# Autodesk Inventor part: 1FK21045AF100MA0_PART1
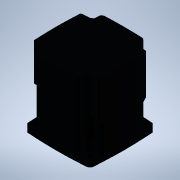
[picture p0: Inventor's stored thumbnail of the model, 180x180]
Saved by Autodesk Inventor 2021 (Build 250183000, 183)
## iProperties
Created: 2025-04
Part Number: 1FK21045AF100MA0_PART1
Material: Generic
Catalog Web Link: www.3dfindit.com
Description: -Servo synchronous motor
Document SubType Name: Modeling
Designer: psAdmin
Mass: 473.602 g
Surface Area: 436.509 cm^2
Volume: 473.602 cm^3
Density: 1 g/cm^3
Appearance: PSOLRGB-176-176-176
Category: PARTsolutions
Title: 1FK21045AF100MA0_PART1
Author: Cadenas PARTsolutions
Comments: Servo synchronous motor
Sending System: PARTsolutions
Preprocessor: ST-DEVELOPER v19.3
PSOL_IDENT_0: {$CADENAS_DATA/23d-libs/siemens_ag/_cat_/52/6b/1fk21045af100ma0.prj},213 {VTYP=3D},{NB=1FK21045AF100
PSOL_IDENT_1: MA0_PART1},{LINA=1FK21045AF100MA0_PART1},{NN=1FK21045AF100MA0_PART1},{NOPRJ=TRUE},{DATE=19.08.2025 1
PSOL_IDENT_2: 4:00:38},{GEOMDATE=30.07.2025 02:01:45},{VERSION=},{LINEID=10},{WBVAR=},{WBNUMERIC=}  {NB=1FK21045AF
PSOL_IDENT_3: 100MA0_PART1},{LINA=1FK21045AF100MA0_PART1},{KT=DUMMY},{PREVIEW=../../../_pool_/cb/72/p_d211_xx_0043
PSOL_IDENT_4: 4j.png},{DESCSHORT=SIMOTICS S-1FK2 HD, SINAMICS S210 3AC 400V-480V, 2.4 Nm, 3000 rpm},{DESCLONG=SIMO
PSOL_IDENT_5: TICS S-1FK2 HD servo motor M0=2.4 Nm; PN = 0.75 kW at nN=3000 rpm (380-480 V); PN = 0.375 kW at nN=1
PSOL_IDENT_6: 500 rpm (200-240 V); with holding brake; degree of protection IP64; cylindrical shaft D19x40mm; abso
PSOL_IDENT_7: lute encoder 22-bit + 12-bit multiturn (encoder AM22DQC); with OCC interface; plug size M17, rotatab
PSOL_IDENT_8: le; SIMOTICS S-1FK2 servomotorfor a wide range of uses in industrial environments. SIMOTICS S‑1FK2 s
PSOL_IDENT_9: ervomotors are compact synchronous motors with a high dynamic performance that set themselves apart
PSOL_IDENT_10: as a result of their high power density, degree of protection and overload capability. The motors ar
PSOL_IDENT_11: e available in two variants: as High Dynamic variant (highest dynamic performance as a result of the
PSOL_IDENT_12: low intrinsic moment of inertia for applications demanding a high dynamic performance with low move
PSOL_IDENT_13: d masses) - and as Compact variant (precise and stable closed-loop control for medium up to large mo
PSOL_IDENT_14: ved masses as a result of a medium intrinsic moment of inertia). SIMOTICSS‑1FK2 servomotors fully ex
PSOL_IDENT_15: ploit their strengths in a system with the SINAMICSS210 frequency converter and simple connection us
PSOL_IDENT_16: ing the one cable connection (OCC). Advantages include the short control and positioning times, fast
PSOL_IDENT_17: and precise correction of disturbing quantities as well as stable control with a high dynamic perfo
PSOL_IDENT_18: rmance. The servo motors can be configured to address a wide range of requirements. For example with
PSOL_IDENT_19: and without holding brake, IP64 or IP65 degree of protection, singleturn or multiturn absolute enco
PSOL_IDENT_20: ders - to name just a few. Further, the servomotors are available in different shaft heights extendi
PSOL_IDENT_21: ng from 20 to 100. A shaft sealing ring is available to achieve an IP65 degree of protection and for
PSOL_IDENT_22: subsequent mounting at the motor or as spare part. SIMOTICS - the optimum motor for each and every
PSOL_IDENT_23: motion control application.},{INTNO=804766906411},{SUPPLIERALTNO=1FK2104-5AF10-0MA0},{MANUID=1FK2104
PSOL_IDENT_24: 5AF100MA0},{MANUNAME=Siemens},{MANUTYPEDESC=Synchronous motor 1FK2-HD 2.4 NM},{AAU732=SIMOTICS},{AAO
PSOL_IDENT_25: 057=S-1FK2},{AAU734=SIMOTICS S-1FK2 HD servo motor M0=2.4 Nm; PN = 0.75 kW at nN=3000 rpm (380-480 V
PSOL_IDENT_26: ); PN = 0.375 kW at nN=1500 rpm (200-240 V); with holding brake; degree of protection IP64; cylindri
PSOL_IDENT_27: cal shaft D19x40mm; absolute encoder 22-bit + 12-bit multiturn (encoder AM22DQC); with OCC interface
PSOL_IDENT_28: ; plug size M17, rotatable;},{AAW338=Synchronous motor 1FK2-HD 2.4 NM},{AAO742=SIMOTICS},{AAO663=404
PSOL_IDENT_29: 2948693070},{NOCUPEROU=1},{PRICEQUANTITY=1},{QUANTITYMIN=1},{QUANTITYINT=1},{CTN=85015100},{COO=DE},
PSOL_IDENT_30: {AAO676=1FK2104-5AF10-0MA0},{AAO677=Siemens AG},{ORDERUNIT=C62},{CONTENTUNIT=C62}
NB: 1FK21045AF100MA0_PART1
NT: Servo synchronous motor
NBSYN: $MANUID._PART1
LINA: 1FK21045AF100MA0_PART1
CATALOG: SIEMENS
PREVIEW: ../../../_pool_/cb/72/p_d211_xx_00434j.png
DESCSHORT: SIMOTICS S-1FK2 HD, SINAMICS S210 3AC 400V-480V, 2.4 Nm, 3000 rpm
DESCLONG: SIMOTICS S-1FK2 HD servo motor M0=2.4 Nm; PN = 0.75 kW at nN=3000 rpm (380-480 V); PN = 0.375 kW at nN=1500 rpm (200-240 V); with holding brake; degree of prote
INTNO: 804766906411
SUPPLIERALTNO: 1FK2104-5AF10-0MA0
MANUID: 1FK21045AF100MA0
MANUNAME: Siemens
MANUTYPEDESC: Synchronous motor 1FK2-HD 2.4 NM
AAU732: SIMOTICS
AAO057: S-1FK2
AAU734: SIMOTICS S-1FK2 HD servo motor M0=2.4 Nm; PN = 0.75 kW at nN=3000 rpm (380-480 V); PN = 0.375 kW at nN=1500 rpm (200-240 V); with holding brake; degree of prote
AAW338: Synchronous motor 1FK2-HD 2.4 NM
AAO742: SIMOTICS
AAO663: 4042948693070.0
NOCUPEROU: 1
PRICEQUANTITY: 1
QUANTITYMIN: 1
QUANTITYINT: 1
CTN: 85015100
COO: DE
ARTICLENO: 1FK21045AF100MA0_PART1
BOMINFO: 1FK21045AF100MA0_PART1
CREATOR: CADENAS GmbH
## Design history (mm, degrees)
feature "2025_04_17_15_34_52_0161"
node "ECLASS_CAX_IMPORTER_001_CP_0_XY"
node "ECLASS_CAX_IMPORTER_001_CP_0_YZ"
node "ECLASS_CAX_IMPORTER_001_CP_0_ZX"
node "ECLASS_CAX_IMPORTER_001_CP_0_X"
node "ECLASS_CAX_IMPORTER_001_CP_0_Y"
node "ECLASS_CAX_IMPORTER_001_CP_0_Z"
node "ECLASS_CAX_IMPORTER_001_CP_0_Center"
node "ECLASS_CAX_IMPORTER_001_CP_1_XY"
node "ECLASS_CAX_IMPORTER_001_CP_1_YZ"
node "ECLASS_CAX_IMPORTER_001_CP_1_ZX"
node "ECLASS_CAX_IMPORTER_001_CP_1_X"
node "ECLASS_CAX_IMPORTER_001_CP_1_Y"
node "ECLASS_CAX_IMPORTER_001_CP_1_Z"
node "ECLASS_CAX_IMPORTER_001_CP_1_Center"
body "Solid1"
